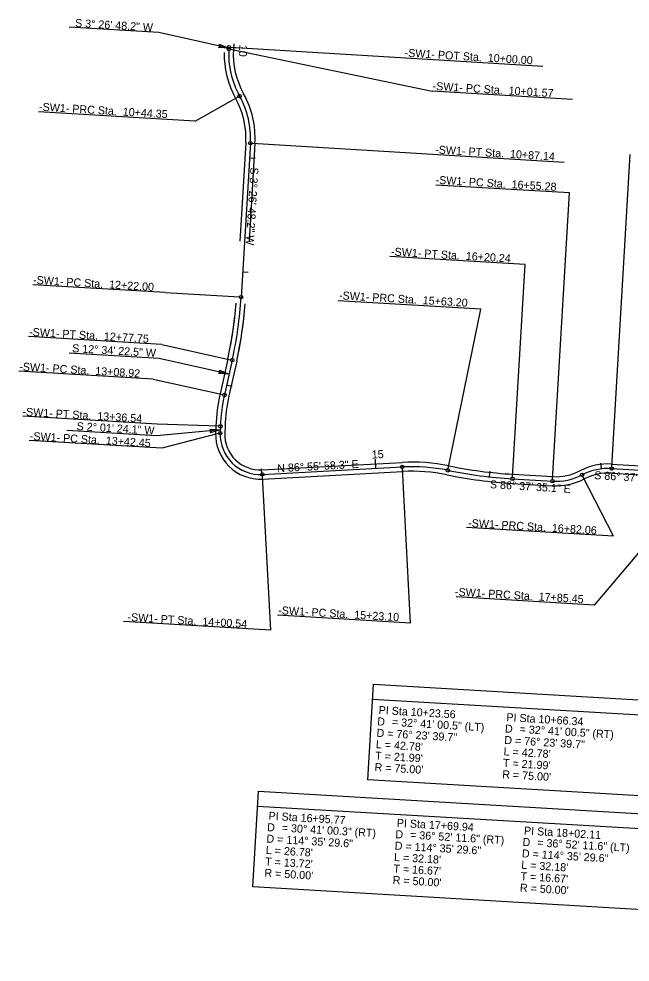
# Model space of a CAD drawing. Extents: x 2011926 to 2013370, y 444604 to 445429.
# Drawn here: x 2011926 to 2012461, y 444604 to 445429 of the extents above; entities that cross this region are included whole.
import ezdxf

# ---------------------------------------------------------------- set-up
doc = ezdxf.new("R2010")
doc.units = 0
for name, color, linetype in [('CTL Secondary Horizontal and Vertical CELL', 7, 'Continuous'), ('Exist Roads EOP', 7, 'Continuous'), ('Exist Structure Minor Drop Inlet Cogo Number', 7, 'Continuous'), ('Exist Structure Minor Pipes RCP 18 Inch', 7, 'Continuous'), ('Exist Structure Minor Pipes RCP 18 Inch Cogo Point CELL', 7, 'Continuous'), ('Exist Structure Minor Pipes RCP 24 Inch Cogo Point CELL', 7, 'Continuous'), ('Exist Structure Minor Pipes RCP 36 Inch', 7, 'Continuous'), ('Exist Utilities Sanitary Sewer UG Line', 7, 'Continuous'), ('Exist Utilities Sanitary Sewer UG Line Cogo Number', 7, 'Continuous')]:
    doc.layers.add(name, color=color, linetype=linetype)

msp = doc.modelspace()

# ---------------------------------------------------------------- linework, layer by layer
at = {"layer": 'CTL Secondary Horizontal and Vertical CELL'}
for p, q in [((2012114.44, 445407.05), (2012114.15, 445402.26)), ((2012125.01, 445320.46), (2012119.83, 445234.55)), ((2012132.99, 445319.98), (2012127.81, 445233.89)), ((2012109.23, 445131.33), (2012102.44, 445100.9)), ((2012109.23, 445131.33), (2012102.44, 445100.9)), ((2012117.03, 445129.59), (2012110.25, 445099.16)), ((2012117.03, 445129.59), (2012110.25, 445099.16)), ((2012098.84, 445072.81), (2012098.63, 445066.91)), ((2012098.84, 445072.81), (2012098.63, 445066.91)), ((2012106.84, 445072.53), (2012106.63, 445066.62)), ((2012106.84, 445072.53), (2012106.63, 445066.62)), ((2012139.27, 445034.57), (2012261.65, 445041.13)), ((2012139.27, 445034.57), (2012261.65, 445041.13)), ((2012445.24, 445039.69), (2012489.6, 445037.07)), ((2012139.7, 445026.59), (2012262.08, 445033.14)), ((2012139.7, 445026.59), (2012262.08, 445033.14)), ((2012358.49, 445030.78), (2012393.47, 445028.71)), ((2012358.49, 445030.78), (2012393.47, 445028.71)), ((2012444.77, 445031.7), (2012489.13, 445029.09)), ((2012358.02, 445022.79), (2012393, 445020.73)), ((2012358.02, 445022.79), (2012393, 445020.73))]:
    msp.add_line(p, q, dxfattribs=at)
for centre, radius, start, end in [((2012185.03, 445398), 79, 178.87516, 209.23674), ((2012185.03, 445398), 71, 176.55328, 209.23674), ((2012054.13, 445324.73), 71, 356.55328, 29.23674), ((2012054.13, 445324.73), 79, 356.55328, 29.23674), ((2011771.52, 445206.65), 346, 347.42708, 355.6193), ((2011771.52, 445206.65), 354, 347.42708, 355.65492), ((2011771.52, 445206.65), 346, 347.42708, 353.78126), ((2011771.52, 445206.65), 354, 347.42708, 353.93786), ((2012252.75, 445067.38), 154, 167.42708, 177.97664), ((2012252.75, 445067.38), 154, 167.42708, 177.97664), ((2012252.75, 445067.38), 146, 167.42708, 177.97664), ((2012252.75, 445067.38), 146, 167.42708, 177.97664), ((2012137.61, 445065.53), 39, 177.97664, 273.06714), ((2012137.61, 445065.53), 39, 177.97664, 273.06714), ((2012137.61, 445065.53), 31, 177.97664, 273.06714), ((2012137.61, 445065.53), 31, 177.97664, 273.06714), ((2012270.28, 444880.14), 161.23, 78.456, 93.06714), ((2012270.28, 444880.14), 161.23, 78.456, 93.06714), ((2012381.79, 445426.09), 396, 258.456, 266.62643), ((2012381.79, 445426.09), 396, 258.456, 266.62643), ((2012442.06, 444985.78), 54, 86.62643, 117.30984), ((2012442.06, 444985.78), 54, 86.62643, 117.30984), ((2012270.28, 444880.14), 153.23, 78.456, 93.06714), ((2012270.28, 444880.14), 153.23, 78.456, 93.06714), ((2012381.79, 445426.09), 404, 258.456, 266.62643), ((2012381.79, 445426.09), 404, 258.456, 266.62643), ((2012396.18, 445074.63), 54, 266.62643, 297.30984), ((2012396.18, 445074.63), 54, 266.62643, 297.30984), ((2012396.18, 445074.63), 46, 266.62643, 297.30984), ((2012396.18, 445074.63), 46, 266.62643, 297.30984), ((2012442.06, 444985.78), 46, 86.62643, 117.30984), ((2012442.06, 444985.78), 46, 86.62643, 117.30984)]:
    msp.add_arc(centre, radius, start, end, dxfattribs=at)
at = {"layer": 'Exist Roads EOP'}
for points in [[(2012101.76, 445406.76), (2012110.21, 445403.29), (2012101.03, 445403.69), (2012102.5, 445405.01)], [(2012101.98, 445121.82), (2012110.43, 445118.35), (2012101.25, 445118.75), (2012102.72, 445120.07)], [(2012093.62, 445070.2), (2012102.73, 445069.47), (2012093.86, 445067.06), (2012094.86, 445068.76)]]:
    msp.add_lwpolyline(points, close=True, dxfattribs=at)
at = {"layer": 'Exist Structure Minor Drop Inlet Cogo Number'}
for p, q in [((2012110.26, 445404.07), (2012110.16, 445402.5)), ((2012110.26, 445404.07), (2012110.16, 445402.5)), ((2012129, 445320.22), (2012120.89, 445185.6)), ((2012129, 445320.22), (2012120.89, 445185.6)), ((2012113.13, 445130.46), (2012106.34, 445100.03)), ((2012113.13, 445130.46), (2012106.34, 445100.03)), ((2012102.84, 445072.67), (2012102.63, 445066.76)), ((2012102.84, 445072.67), (2012102.63, 445066.76)), ((2012139.48, 445030.58), (2012261.87, 445037.14)), ((2012139.48, 445030.58), (2012261.87, 445037.14)), ((2012445, 445035.69), (2012489.36, 445033.08)), ((2012445, 445035.69), (2012489.36, 445033.08)), ((2012358.25, 445026.78), (2012393.24, 445024.72)), ((2012358.25, 445026.78), (2012393.24, 445024.72))]:
    msp.add_line(p, q, dxfattribs=at)
for centre, radius, start, end in [((2012185.03, 445398), 75, 176.55328, 209.23674), ((2012185.03, 445398), 75, 176.55328, 209.23674), ((2012054.13, 445324.73), 75, 356.55328, 29.23674), ((2012054.13, 445324.73), 75, 356.55328, 29.23674), ((2011771.52, 445206.65), 350, 347.42708, 356.55328), ((2011771.52, 445206.65), 350, 347.42708, 356.55328), ((2012252.75, 445067.38), 150, 167.42708, 177.97664), ((2012252.75, 445067.38), 150, 167.42708, 177.97664), ((2012137.61, 445065.53), 35, 177.97664, 273.06714), ((2012270.28, 444880.14), 157.23, 78.456, 93.06714), ((2012270.28, 444880.14), 157.23, 78.456, 93.06714), ((2012442.06, 444985.78), 50, 86.62643, 117.30984), ((2012442.06, 444985.78), 50, 86.62643, 117.30984), ((2012381.79, 445426.09), 400, 258.456, 266.62643), ((2012381.79, 445426.09), 400, 258.456, 266.62643), ((2012396.18, 445074.63), 50, 266.62643, 297.30984), ((2012396.18, 445074.63), 50, 266.62643, 297.30984)]:
    msp.add_arc(centre, radius, start, end, dxfattribs=at)
at = {"layer": 'Exist Structure Minor Pipes RCP 18 Inch'}
for p, q in [((2012110.26, 445404.07), (2012118.24, 445403.59)), ((2012238.8, 445035.9), (2012238.37, 445043.89))]:
    msp.add_line(p, q, dxfattribs=at)
at = {"layer": 'Exist Structure Minor Pipes RCP 24 Inch Cogo Point CELL'}
for p, q in [((2012128.22, 445307.38), (2012133.22, 445307.08)), ((2012122.21, 445207.56), (2012127.2, 445207.26)), ((2012108.29, 445108.74), (2012113.17, 445107.65)), ((2012138.94, 445030.55), (2012138.75, 445035.55)), ((2012436.18, 445035.43), (2012435.6, 445040.4)), ((2012338.09, 445028.48), (2012338.64, 445033.45))]:
    msp.add_line(p, q, dxfattribs=at)
at = {"layer": 'Exist Utilities Sanitary Sewer UG Line'}
for p, q in [((2012235.82, 444834.24), (2013117.6, 444782.26)), ((2012135.32, 444740.69), (2013252.58, 444674.83))]:
    msp.add_line(p, q, dxfattribs=at)
for points in [[(2012236.58, 444847.2), (2013118.36, 444795.22), (2013113.44, 444711.71), (2012231.66, 444763.68)], [(2012136.08, 444753.64), (2013253.34, 444687.78), (2013248.42, 444604.27), (2012131.16, 444670.13)]]:
    msp.add_lwpolyline(points, close=True, dxfattribs=at)
at = {"layer": 'Exist Utilities Sanitary Sewer UG Line Cogo Number'}
for p, q in [((2012049.06, 445416.92), (2011970.55, 445421.55)), ((2012110.21, 445403.29), (2012049.06, 445416.92)), ((2012111.63, 445402.2), (2012288.15, 445365.52)), ((2012111.75, 445403.98), (2012384.76, 445387.54)), ((2012410.62, 445358.3), (2012288.15, 445365.52)), ((2012080.58, 445339.53), (2012118.27, 445360.63)), ((2012080.58, 445339.53), (2011943.55, 445347.61)), ((2012130.5, 445320.13), (2012403.5, 445303.69)), ((2012445.09, 445037.19), (2012461.18, 445310.22)), ((2012408.09, 445276.65), (2012291.24, 445283.54)), ((2012393.32, 445026.22), (2012408.09, 445276.65)), ((2012369.3, 445214.11), (2012250.96, 445221.09)), ((2012358.34, 445028.28), (2012369.3, 445214.11)), ((2012054.85, 445189.58), (2011938.68, 445196.43)), ((2012054.85, 445189.58), (2012119.39, 445185.7)), ((2012330.52, 445175.06), (2012205.7, 445182.42)), ((2012302.04, 445035.65), (2012330.52, 445175.06)), ((2012051.47, 445144.21), (2011934.81, 445151.09)), ((2012051.47, 445144.21), (2012111.67, 445130.78)), ((2012049.09, 445132.03), (2011970.59, 445136.65)), ((2012110.43, 445118.35), (2012049.09, 445132.03)), ((2012044, 445113.93), (2011926.5, 445120.86)), ((2012044, 445113.93), (2012104.88, 445100.36)), ((2012047.44, 445074.63), (2011929.9, 445081.56)), ((2012046.95, 445064.39), (2011968.45, 445069.02)), ((2012102.73, 445069.47), (2012046.95, 445064.39)), ((2012101.34, 445072.73), (2012047.44, 445074.63)), ((2012051.61, 445053.51), (2011935.41, 445060.36)), ((2012101.18, 445066.39), (2012051.61, 445053.51)), ((2012269.18, 444900.62), (2012261.95, 445035.64)), ((2012146.77, 444894.58), (2012139.56, 445029.08)), ((2012446.76, 444976.68), (2012419.81, 445028.88)), ((2012429.9, 444916.39), (2012517.75, 445020.19)), ((2012446.76, 444976.68), (2012318.05, 444984.27)), ((2012429.9, 444916.39), (2012308.94, 444923.52)), ((2012269.18, 444900.62), (2012152.82, 444907.48)), ((2012146.77, 444894.58), (2012018.03, 444902.17))]:
    msp.add_line(p, q, dxfattribs=at)
for centre in [(2012110.16, 445402.5), (2012110.26, 445404.07), (2012119.58, 445361.36), (2012129, 445320.22), (2012120.89, 445185.6), (2012113.13, 445130.46), (2012106.34, 445100.03), (2012102.63, 445066.76), (2012102.84, 445072.67), (2012261.87, 445037.14), (2012301.74, 445034.18), (2012445, 445035.69), (2012139.48, 445030.58), (2012358.25, 445026.78), (2012419.12, 445030.21), (2012393.24, 445024.72)]:
    msp.add_circle(centre, 1.5, dxfattribs=at)

# ---------------------------------------------------------------- texts
at = {"layer": 'Exist Structure Minor Pipes RCP 18 Inch Cogo Point CELL'}
for s, rotation, p in [('10', 266.55328, (2012119.44, 445406.33)), ('15', 3.06714, (2012235.39, 445044.41))]:
    msp.add_text(s, height=7, rotation=rotation, dxfattribs=at).set_placement(p)
at = {"layer": 'Exist Structure Minor Pipes RCP 36 Inch'}
for s, rotation, p in [('S 3%%d 26\' 48.2" W', 356.62643, (2011975.5, 445421.85)), ('S 3%%d 26\' 48.2" W', 266.55328, (2012129.12, 445299.15)), ('S 12%%d 34\' 22.5" W', 356.62643, (2011972.94, 445137.56)), ('S 2%%d 01\' 24.1" W', 356.62643, (2011976.85, 445069.39)), ('N 86%%d 55\' 58.3" E', 3.06714, (2012152.65, 445032.48)), ('S 86%%d 37\' 35.1" E', 356.62643, (2012429.63, 445026.55)), ('S 86%%d 37\' 35.1" E', 356.62643, (2012338.38, 445018.57))]:
    msp.add_text(s, height=7, rotation=rotation, dxfattribs=at).set_placement(p)
at = {"layer": 'Exist Utilities Sanitary Sewer UG Line'}
for s, p in [('PI Sta 10+23.56', (2012241.06, 444821.24)), ('PI Sta 10+66.34', (2012352.79, 444814.99)), ('D', (2012239.8, 444811.3)), ('= 32%%d 41\' 00.5" (LT)', (2012252.65, 444810.84)), ('D', (2012351.53, 444805.05)), ('D = 76%%d 23\' 39.7"', (2012239.21, 444801.32)), ('= 32%%d 41\' 00.5" (RT)', (2012364.37, 444804.59)), ("L = 42.78'", (2012238.62, 444791.33)), ('D = 76%%d 23\' 39.7"', (2012350.94, 444795.07)), ("T = 21.99'", (2012238.03, 444781.35)), ("L = 42.78'", (2012350.35, 444785.08)), ("T = 21.99'", (2012349.76, 444775.1)), ("R = 75.00'", (2012237.45, 444771.37)), ("R = 75.00'", (2012349.17, 444765.12)), ('PI Sta 16+95.77', (2012144.74, 444728.79)), ('PI Sta 17+69.94', (2012256.93, 444722.62)), ('D', (2012143.48, 444718.85)), ('= 30%%d 41\' 00.3" (RT)', (2012156.33, 444718.39)), ('PI Sta 18+02.11', (2012368.19, 444715.85)), ('D = 114%%d 35\' 29.6"', (2012142.9, 444708.87)), ('D', (2012255.67, 444712.68)), ('= 36%%d 52\' 11.6" (RT)', (2012268.52, 444712.21)), ("L = 26.78'", (2012142.31, 444698.88)), ('D = 114%%d 35\' 29.6"', (2012255.08, 444702.69)), ('D', (2012366.93, 444705.91)), ('= 36%%d 52\' 11.6" (LT)', (2012379.77, 444705.44)), ("L = 32.18'", (2012254.49, 444692.71)), ('D = 114%%d 35\' 29.6"', (2012366.34, 444695.92)), ("T = 13.72'", (2012141.72, 444688.9)), ("T = 16.67'", (2012253.91, 444682.73)), ("L = 32.18'", (2012365.75, 444685.94)), ("R = 50.00'", (2012141.13, 444678.92)), ("T = 16.67'", (2012365.16, 444675.96)), ("R = 50.00'", (2012253.32, 444672.74)), ("R = 50.00'", (2012364.57, 444665.98))]:
    msp.add_text(s, height=7, rotation=356.62643, dxfattribs=at).set_placement(p)
at = {"layer": 'Exist Utilities Sanitary Sewer UG Line Cogo Number'}
for s, rotation, p in [('-SW1- POT Sta.  10+00.00', 356.55328, (2012263.8, 445395.79)), ('-SW1- PC Sta.  10+01.57', 356.55328, (2012288.27, 445366.7)), ('-SW1- PRC Sta.  10+44.35', 356.62643, (2011944.01, 445348.59)), ('-SW1- PT Sta.  10+87.14', 356.55328, (2012290.51, 445311.25)), ('-SW1- PC Sta.  16+55.28', 356.62643, (2012290.87, 445284.69)), ('-SW1- PT Sta.  16+20.24', 356.62643, (2012251.89, 445222.02)), ('-SW1- PC Sta.  12+22.00', 356.55328, (2011938.78, 445197.28)), ('-SW1- PRC Sta.  15+63.20', 356.62643, (2012206.41, 445183.76)), ('-SW1- PT Sta.  12+77.75', 356.62643, (2011935.32, 445151.83)), ('-SW1- PC Sta.  13+08.92', 356.62643, (2011926.7, 445121.55)), ('-SW1- PT Sta.  13+36.54', 356.62643, (2011929.51, 445082.07)), ('-SW1- PC Sta.  13+42.45', 356.62643, (2011935.94, 445060.75)), ('-SW1- PRC Sta.  16+82.06', 356.62643, (2012319.36, 444984.78)), ('-SW1- PRC Sta.  17+85.45', 356.62643, (2012307.81, 444924.67)), ('-SW1- PC Sta.  15+23.10', 356.62643, (2012153.22, 444908.49)), ('-SW1- PT Sta.  14+00.54', 356.62643, (2012021.36, 444902.52))]:
    msp.add_text(s, height=7, rotation=rotation, dxfattribs=at).set_placement(p)

doc.saveas('drawing.dxf')
